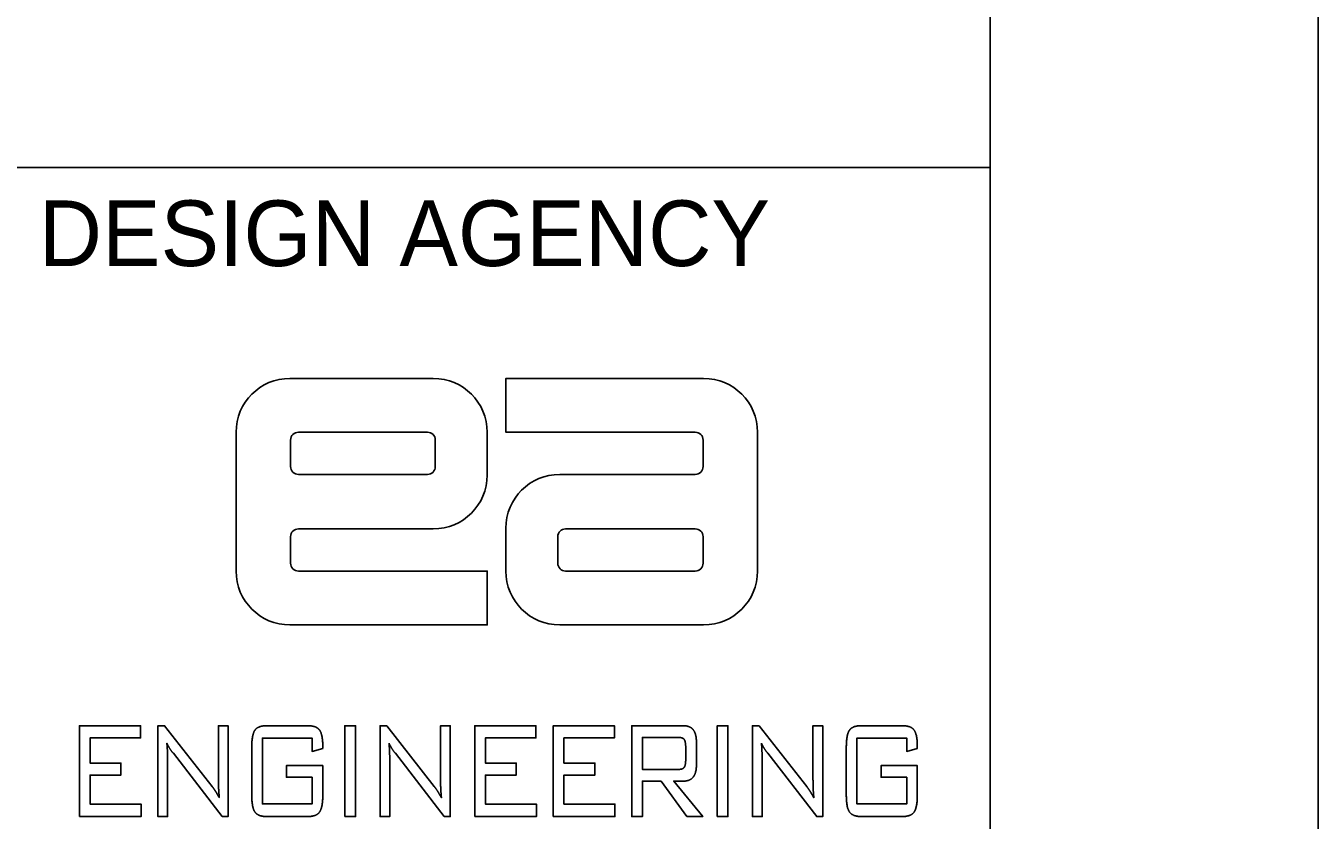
# Model space of a CAD drawing. Extents: x 0 to 34, y 0 to 22.
# Drawn here: x 32.03 to 34, y 3.506 to 4.716 of the extents above; entities that cross this region are included whole.
import ezdxf

# ---------------------------------------------------------------- set-up
doc = ezdxf.new("R2010")
doc.units = 0
for name, color, linetype in [('SH_Border', 7, 'Continuous'), ('SH_Cut_Line', 7, 'Continuous'), ('SH_Data', 7, 'Continuous'), ('TX_X_20', 7, 'Continuous')]:
    doc.layers.add(name, color=color, linetype=linetype)

msp = doc.modelspace()

# ---------------------------------------------------------------- linework, layer by layer
at = {"layer": 'SH_Border'}
msp.add_line((32, 4.5), (33.5, 4.5), dxfattribs=at)
msp.add_lwpolyline([(1.5, 21.5), (33.5, 21.5), (33.5, 0.5), (1.5, 0.5)], close=True, dxfattribs=at)
at = {"layer": 'SH_Cut_Line'}
msp.add_lwpolyline([(0, 0), (34, 0), (34, 22), (0, 22)], close=True, dxfattribs=at)
at = {"layer": 'TX_X_20'}
for p, q in [((32.6515, 4.1788), (32.433, 4.1788)), ((32.433, 4.1788), (32.6515, 4.1788)), ((32.762, 4.1788), (33.0635, 4.1788)), ((32.762, 4.0967), (32.762, 4.1788)), ((32.351, 4.0967), (32.351, 3.8852)), ((32.351, 3.8852), (32.351, 4.0967)), ((32.4459, 4.0967), (32.6426, 4.0967)), ((32.6426, 4.0967), (32.4459, 4.0967)), ((32.7336, 4.0315), (32.7336, 4.0967)), ((32.7336, 4.0967), (32.7336, 4.0315)), ((33.0507, 4.0967), (32.762, 4.0967)), ((33.1456, 3.8852), (33.1456, 4.0967)), ((33.1456, 4.0967), (33.1456, 3.8852)), ((32.434, 4.0444), (32.434, 4.0849)), ((32.434, 4.0849), (32.434, 4.0444)), ((32.6545, 4.0849), (32.6545, 4.0444)), ((32.6545, 4.0444), (32.6545, 4.0849)), ((33.0626, 4.0849), (33.0626, 4.0444)), ((33.0626, 4.0444), (33.0626, 4.0849)), ((32.6426, 4.0325), (32.4459, 4.0325)), ((32.4459, 4.0325), (32.6426, 4.0325)), ((33.0507, 4.0325), (32.8441, 4.0325)), ((32.8441, 4.0325), (33.0507, 4.0325)), ((32.4459, 3.9494), (32.6515, 3.9494)), ((32.6515, 3.9494), (32.4459, 3.9494)), ((32.762, 3.9504), (32.762, 3.8852)), ((32.762, 3.8852), (32.762, 3.9504)), ((32.853, 3.9494), (33.0507, 3.9494)), ((33.0507, 3.9494), (32.853, 3.9494)), ((32.434, 3.8971), (32.434, 3.9376)), ((32.434, 3.9376), (32.434, 3.8971)), ((32.8411, 3.8971), (32.8411, 3.9376)), ((32.8411, 3.9376), (32.8411, 3.8971)), ((33.0626, 3.9376), (33.0626, 3.8971)), ((33.0626, 3.8971), (33.0626, 3.9376)), ((32.4459, 3.8852), (32.7336, 3.8852)), ((32.7336, 3.8852), (32.7336, 3.8031)), ((33.0507, 3.8852), (32.853, 3.8852)), ((32.853, 3.8852), (33.0507, 3.8852)), ((32.7336, 3.8031), (32.433, 3.8031)), ((32.8441, 3.8031), (33.0635, 3.8031)), ((33.0635, 3.8031), (32.8441, 3.8031)), ((32.3975, 3.6495), (32.4602, 3.6495)), ((33.3037, 3.6495), (33.3663, 3.6495)), ((32.3748, 3.5439), (32.3748, 3.6168)), ((33.0361, 3.6173), (33.0361, 3.5971)), ((33.0526, 3.5917), (33.0526, 3.6227)), ((33.2809, 3.5439), (33.2809, 3.6168)), ((32.4602, 3.5111), (32.3975, 3.5111)), ((33.3663, 3.5111), (33.3037, 3.5111))]:
    msp.add_line(p, q, dxfattribs=at)
for points in [[(33.0635, 4.1788), (32.762, 4.1788), (32.762, 4.0967), (33.0507, 4.0967)], [(32.433, 3.8031), (32.7336, 3.8031), (32.7336, 3.8852), (32.4459, 3.8852)], [(32.2465, 3.5927), (32.2465, 3.5111), (32.2317, 3.5111), (32.2317, 3.6495), (32.2419, 3.6495), (32.3144, 3.5569)], [(32.3239, 3.5736), (32.3239, 3.6495), (32.3387, 3.6495), (32.3387, 3.5111), (32.3297, 3.5111), (32.2553, 3.6074)], [(32.5851, 3.5927), (32.5851, 3.5111), (32.5703, 3.5111), (32.5703, 3.6495), (32.5804, 3.6495), (32.6529, 3.5569)], [(32.6625, 3.5736), (32.6625, 3.6495), (32.6773, 3.6495), (32.6773, 3.5111), (32.6682, 3.5111), (32.5938, 3.6074)], [(33.032, 3.6495), (32.954, 3.6495), (32.954, 3.5111), (32.9702, 3.5111), (32.9702, 3.565), (32.9987, 3.565), (33.0381, 3.5111), (33.0621, 3.5111), (33.0178, 3.565), (33.032, 3.565)], [(33.1527, 3.5927), (33.1527, 3.5111), (33.1379, 3.5111), (33.1379, 3.6495), (33.148, 3.6495), (33.2205, 3.5569)], [(33.2301, 3.5736), (33.2301, 3.6495), (33.2449, 3.6495), (33.2449, 3.5111), (33.2358, 3.5111), (33.1614, 3.6074)], [(32.483, 3.6183), (32.483, 3.6149), (32.4668, 3.6103), (32.4668, 3.6307), (32.3909, 3.6307), (32.3909, 3.5304), (32.4668, 3.5304), (32.4668, 3.571), (32.4276, 3.571), (32.4276, 3.5886), (32.483, 3.5886), (32.483, 3.5439)], [(33.0257, 3.5829), (32.9702, 3.5829), (32.9702, 3.6316), (33.0257, 3.6316)], [(33.3891, 3.6183), (33.3891, 3.6149), (33.3729, 3.6103), (33.3729, 3.6307), (33.2971, 3.6307), (33.2971, 3.5304), (33.3729, 3.5304), (33.3729, 3.571), (33.3338, 3.571), (33.3338, 3.5886), (33.3891, 3.5886), (33.3891, 3.5439)]]:
    msp.add_lwpolyline(points, dxfattribs=at)
for points in [[(32.1121, 3.5111), (32.1121, 3.6495), (32.2053, 3.6495), (32.2053, 3.631), (32.1283, 3.631), (32.1283, 3.5925), (32.1754, 3.5925), (32.1754, 3.5742), (32.1283, 3.5742), (32.1283, 3.5301), (32.2061, 3.5301), (32.2061, 3.5111)], [(32.5166, 3.5111), (32.5166, 3.6495), (32.5329, 3.6495), (32.5329, 3.5111)], [(32.7147, 3.5111), (32.7147, 3.6495), (32.8079, 3.6495), (32.8079, 3.631), (32.7309, 3.631), (32.7309, 3.5925), (32.778, 3.5925), (32.778, 3.5742), (32.7309, 3.5742), (32.7309, 3.5301), (32.8087, 3.5301), (32.8087, 3.5111)], [(32.8343, 3.5111), (32.8343, 3.6495), (32.9276, 3.6495), (32.9276, 3.631), (32.8506, 3.631), (32.8506, 3.5925), (32.8977, 3.5925), (32.8977, 3.5742), (32.8506, 3.5742), (32.8506, 3.5301), (32.9283, 3.5301), (32.9283, 3.5111)], [(33.0842, 3.5111), (33.0842, 3.6495), (33.1005, 3.6495), (33.1005, 3.5111)]]:
    msp.add_lwpolyline(points, close=True, dxfattribs=at)
for centre, radius, start, end in [((32.433, 4.0967), 0.0821, 90, 180), ((32.433, 4.0967), 0.0821, 90, 180), ((32.6515, 4.0967), 0.0821, 0, 90), ((32.6515, 4.0967), 0.0821, 0, 90), ((33.0635, 4.0967), 0.0821, 0, 90), ((33.0635, 4.0967), 0.0821, 0, 90), ((32.4459, 4.0849), 0.0119, 90, 180), ((32.4459, 4.0849), 0.0119, 90, 180), ((32.6426, 4.0849), 0.0119, 0, 90), ((32.6426, 4.0849), 0.0119, 0, 90), ((33.0507, 4.0849), 0.0119, 0, 90), ((33.0507, 4.0849), 0.0119, 0, 90), ((32.4459, 4.0444), 0.0119, 180, 270), ((32.4459, 4.0444), 0.0119, 180, 270), ((32.6426, 4.0444), 0.0119, 270, 0), ((32.6426, 4.0444), 0.0119, 270, 0), ((33.0507, 4.0444), 0.0119, 270, 0), ((33.0507, 4.0444), 0.0119, 270, 0), ((32.6515, 4.0315), 0.0821, 270, 360), ((32.6515, 4.0315), 0.0821, 270, 360), ((32.8441, 3.9504), 0.0821, 90, 180), ((32.8441, 3.9504), 0.0821, 90, 180), ((32.4459, 3.9376), 0.0119, 90, 180), ((32.4459, 3.9376), 0.0119, 90, 180), ((32.853, 3.9376), 0.0119, 90, 180), ((32.853, 3.9376), 0.0119, 90, 180), ((33.0507, 3.9376), 0.0119, 0, 90), ((33.0507, 3.9376), 0.0119, 0, 90), ((32.433, 3.8852), 0.0821, 180, 270), ((32.433, 3.8852), 0.0821, 180, 270), ((32.4459, 3.8971), 0.0119, 180, 270), ((32.4459, 3.8971), 0.0119, 180, 270), ((32.8441, 3.8852), 0.0821, 180, 270), ((32.8441, 3.8852), 0.0821, 180, 270), ((32.853, 3.8971), 0.0119, 180, 270), ((32.853, 3.8971), 0.0119, 180, 270), ((33.0507, 3.8971), 0.0119, 270, 0), ((33.0507, 3.8971), 0.0119, 270, 0), ((33.0635, 3.8852), 0.0821, 270, 360), ((33.0635, 3.8852), 0.0821, 270, 360)]:
    msp.add_arc(centre, radius, start, end, dxfattribs=at)
for points in [[(32.3795, 3.6426), (32.3842, 3.6495), (32.3975, 3.6495)], [(32.4602, 3.6495), (32.4732, 3.6495), (32.4781, 3.6428)], [(33.0477, 3.6432), (33.0429, 3.6495), (33.032, 3.6495)], [(33.2857, 3.6426), (33.2904, 3.6495), (33.3037, 3.6495)], [(33.3663, 3.6495), (33.3794, 3.6495), (33.3842, 3.6428)], [(32.3748, 3.6168), (32.3748, 3.6356), (32.3795, 3.6426)], [(32.4781, 3.6428), (32.483, 3.636), (32.483, 3.6183)], [(33.0257, 3.6316), (33.0316, 3.6316), (33.0339, 3.6284)], [(33.0339, 3.6284), (33.0361, 3.6252), (33.0361, 3.6173)], [(33.0526, 3.6227), (33.0526, 3.6368), (33.0477, 3.6432)], [(33.2809, 3.6168), (33.2809, 3.6356), (33.2857, 3.6426)], [(33.3842, 3.6428), (33.3891, 3.636), (33.3891, 3.6183)], [(32.2536, 3.6094), (32.2481, 3.6165), (32.2454, 3.6229)], [(32.2454, 3.6229), (32.246, 3.6166), (32.2463, 3.6095)], [(32.2463, 3.6095), (32.2465, 3.6024), (32.2465, 3.5927)], [(32.2553, 3.6074), (32.2547, 3.608), (32.2536, 3.6094)], [(32.5921, 3.6094), (32.5866, 3.6165), (32.584, 3.6229)], [(32.584, 3.6229), (32.5845, 3.6166), (32.5848, 3.6095)], [(32.5848, 3.6095), (32.5851, 3.6024), (32.5851, 3.5927)], [(32.5938, 3.6074), (32.5932, 3.608), (32.5921, 3.6094)], [(33.1597, 3.6094), (33.1542, 3.6165), (33.1516, 3.6229)], [(33.1516, 3.6229), (33.1521, 3.6166), (33.1524, 3.6095)], [(33.1524, 3.6095), (33.1527, 3.6024), (33.1527, 3.5927)], [(33.1614, 3.6074), (33.1608, 3.608), (33.1597, 3.6094)], [(33.0339, 3.5861), (33.0317, 3.5829), (33.0257, 3.5829)], [(33.0361, 3.5971), (33.0361, 3.5892), (33.0339, 3.5861)], [(33.0477, 3.5714), (33.0526, 3.5777), (33.0526, 3.5917)], [(32.3243, 3.5535), (32.3239, 3.5607), (32.3239, 3.5736)], [(32.6628, 3.5535), (32.6625, 3.5607), (32.6625, 3.5736)], [(33.032, 3.565), (33.0429, 3.565), (33.0477, 3.5714)], [(33.2304, 3.5535), (33.2301, 3.5607), (33.2301, 3.5736)], [(32.3144, 3.5569), (32.3169, 3.5538), (32.3197, 3.5493)], [(32.3197, 3.5493), (32.3225, 3.5449), (32.3254, 3.5395)], [(32.3254, 3.5395), (32.3247, 3.5462), (32.3243, 3.5535)], [(32.6529, 3.5569), (32.6554, 3.5538), (32.6582, 3.5493)], [(32.6582, 3.5493), (32.661, 3.5449), (32.6639, 3.5395)], [(32.6639, 3.5395), (32.6632, 3.5462), (32.6628, 3.5535)], [(33.2205, 3.5569), (33.223, 3.5538), (33.2258, 3.5493)], [(33.2258, 3.5493), (33.2286, 3.5449), (33.2315, 3.5395)], [(33.2315, 3.5395), (33.2308, 3.5462), (33.2304, 3.5535)], [(32.3795, 3.5181), (32.3748, 3.525), (32.3748, 3.5439)], [(32.483, 3.5439), (32.483, 3.5249), (32.4782, 3.518)], [(33.2857, 3.5181), (33.2809, 3.525), (33.2809, 3.5439)], [(33.3891, 3.5439), (33.3891, 3.5249), (33.3843, 3.518)], [(32.3975, 3.5111), (32.3842, 3.5111), (32.3795, 3.5181)], [(32.4782, 3.518), (32.4734, 3.5111), (32.4602, 3.5111)], [(33.3037, 3.5111), (33.2904, 3.5111), (33.2857, 3.5181)], [(33.3843, 3.518), (33.3795, 3.5111), (33.3663, 3.5111)]]:
    msp.add_open_spline(points, degree=2, dxfattribs=at)

# ---------------------------------------------------------------- texts
at = {"layer": 'SH_Data'}
msp.add_text('DESIGN AGENCY', height=0.1, dxfattribs=at).set_placement((32.05, 4.35))

doc.saveas('drawing.dxf')
